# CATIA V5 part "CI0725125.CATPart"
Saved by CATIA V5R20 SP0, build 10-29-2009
Part number: CI0725125
Bounding box of the stored display mesh (mm): x -24 to 24, y -20.111 to 159.5, z -24.221 to 28.662
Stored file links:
  C:\Users\Raffaele\Desktop\3D X SITO CF\BOLEX\19-INCLINED ASSEMBLY REF_CI\CI0725125.CATPart
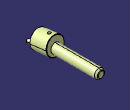
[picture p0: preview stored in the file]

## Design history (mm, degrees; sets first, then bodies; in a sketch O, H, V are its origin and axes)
Set1
  DatumSurface1 to DatumSurface16 "MANIFOLD_SOLID_BREP #389"
  DatumSurface17 to DatumSurface39 "MANIFOLD_SOLID_BREP #1134"
Body1 (main body)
